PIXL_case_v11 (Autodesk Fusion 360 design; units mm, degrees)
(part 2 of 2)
sketch "Sketch25" plane through (0, 0, -9.2) normal (0, 0, 1) x axis (1, 0, 0)
  line L1 (4.375, -8.325) -> (3.775, -8.325)
  line L2 (4.375, -7.725) -> (4.375, -8.325)
  line L3 (3.775, -7.725) -> (4.375, -7.725)
  line L4 (3.775, -8.325) -> (3.775, -7.725)
  line L5 (6.075, -8.325) -> (5.475, -8.325)
  line L6 (6.075, -7.725) -> (6.075, -8.325)
  line L7 (5.475, -7.725) -> (6.075, -7.725)
  line L8 (5.475, -8.325) -> (5.475, -7.725)
  line L9 (3.525, -7.475) -> (2.925, -7.475)
  line L10 (3.525, -6.875) -> (3.525, -7.475)
  line L11 (2.925, -6.875) -> (3.525, -6.875)
  line L12 (2.925, -7.475) -> (2.925, -6.875)
  line L13 (5.225, -7.475) -> (4.625, -7.475)
  line L14 (5.225, -6.875) -> (5.225, -7.475)
  line L15 (4.625, -6.875) -> (5.225, -6.875)
  line L16 (4.625, -7.475) -> (4.625, -6.875)
  line L17 (6.925, -7.475) -> (6.325, -7.475)
  line L18 (6.925, -6.875) -> (6.925, -7.475)
  line L19 (6.325, -6.875) -> (6.925, -6.875)
  line L20 (6.325, -7.475) -> (6.325, -6.875)
  line L21 (2.675, -6.625) -> (2.075, -6.625)
  line L22 (2.675, -6.025) -> (2.675, -6.625)
  line L23 (2.075, -6.025) -> (2.675, -6.025)
  line L24 (2.075, -6.625) -> (2.075, -6.025)
  line L25 (4.375, -6.625) -> (3.775, -6.625)
  line L26 (4.375, -6.025) -> (4.375, -6.625)
  line L27 (3.775, -6.025) -> (4.375, -6.025)
  line L28 (3.775, -6.625) -> (3.775, -6.025)
  line L29 (6.075, -6.625) -> (5.475, -6.625)
  line L30 (6.075, -6.025) -> (6.075, -6.625)
  line L31 (5.475, -6.025) -> (6.075, -6.025)
  line L32 (5.475, -6.625) -> (5.475, -6.025)
  line L33 (3.525, -5.775) -> (2.925, -5.775)
  line L34 (3.525, -5.175) -> (3.525, -5.775)
  line L35 (2.925, -5.175) -> (3.525, -5.175)
  line L36 (2.925, -5.775) -> (2.925, -5.175)
  line L37 (5.225, -5.775) -> (4.625, -5.775)
  line L38 (5.225, -5.175) -> (5.225, -5.775)
  line L39 (4.625, -5.175) -> (5.225, -5.175)
  line L40 (4.625, -5.775) -> (4.625, -5.175)
  line L41 (6.925, -5.775) -> (6.325, -5.775)
  line L42 (6.925, -5.175) -> (6.925, -5.775)
  line L43 (6.325, -5.175) -> (6.925, -5.175)
  line L44 (6.325, -5.775) -> (6.325, -5.175)
  line L45 (2.675, -4.925) -> (2.075, -4.925)
  line L46 (2.675, -4.325) -> (2.675, -4.925)
  line L47 (2.075, -4.325) -> (2.675, -4.325)
  line L48 (2.075, -4.925) -> (2.075, -4.325)
  line L49 (4.375, -4.925) -> (3.775, -4.925)
  line L50 (4.375, -4.325) -> (4.375, -4.925)
  line L51 (3.775, -4.325) -> (4.375, -4.325)
  line L52 (3.775, -4.925) -> (3.775, -4.325)
  line L53 (6.075, -4.925) -> (5.475, -4.925)
  line L54 (6.075, -4.325) -> (6.075, -4.925)
  line L55 (5.475, -4.325) -> (6.075, -4.325)
  line L56 (5.475, -4.925) -> (5.475, -4.325)
  line L57 (3.525, -4.075) -> (2.925, -4.075)
  line L58 (3.525, -3.475) -> (3.525, -4.075)
  line L59 (2.925, -3.475) -> (3.525, -3.475)
  line L60 (2.925, -4.075) -> (2.925, -3.475)
  line L61 (5.225, -4.075) -> (4.625, -4.075)
  line L62 (5.225, -3.475) -> (5.225, -4.075)
  line L63 (4.625, -3.475) -> (5.225, -3.475)
  line L64 (4.625, -4.075) -> (4.625, -3.475)
extrude "Extrude25" cut sketch "Sketch25" along normal blind 0.3
work_plane "WorkPlane26" AlongDistance -9.2 ExtraOffset 0
sketch "Sketch26" plane through (0, 0, -9.2) normal (0, 0, 1) x axis (1, 0, 0)
  line L1 (15.05, -9.65) -> (11.95, -9.65)
  line L2 (17.25, -4.35) -> (17.25, -7.45)
  line L3 (11.95, -2.15) -> (15.05, -2.15)
  line L4 (9.75, -7.45) -> (9.75, -4.35)
  arc A1 centre (15.05, -7.45) radius 2.2 clockwise from (17.25, -7.45) to (15.05, -9.65)
  arc A2 centre (15.05, -4.35) radius 2.2 clockwise from (15.05, -2.15) to (17.25, -4.35)
  arc A3 centre (11.95, -4.35) radius 2.2 clockwise from (9.75, -4.35) to (11.95, -2.15)
  arc A4 centre (11.95, -7.45) radius 2.2 clockwise from (11.95, -9.65) to (9.75, -7.45)
extrude "Extrude26" cut sketch "Sketch26" along normal blind 0.3
work_plane "WorkPlane1" AlongDistance -5.8 ExtraOffset 0
sketch "Sketch1" plane through (0, 0, -5.8) normal (0, 0, 1) x axis (1, 0, 0)
  line L1 (8.4, -6.9) -> (-21.6, -6.9)
  line L2 (8.4, 13.1) -> (8.4, -6.9)
  line L3 (-21.6, 13.1) -> (8.4, 13.1)
  line L4 (-21.6, -6.9) -> (-21.6, 13.1)
extrude "Extrude1" new body sketch "Sketch1" along normal blind 5 bodies "LiPo 30x20x5"
work_plane "WorkPlane2" AlongDistance -6.5 ExtraOffset 0
sketch "Sketch2" plane through (0, 0, -6.5) normal (0, 0, 1) x axis (1, 0, 0)
  circle C1 centre (15.5, 4) radius 5
extrude "Extrude2" new body sketch "Sketch2" along normal blind 2.7 bodies "Vibration motor 10x2.7"
work_plane "WorkPlane3" AlongDistance -1.3 ExtraOffset 0
sketch "Sketch3" plane through (0, 0, -1.3) normal (0, 0, 1) x axis (1, 0, 0)
  line L1 (21.6, -24.9) -> (0.6, -24.9)
  line L2 (21.6, -7.1) -> (21.6, -24.9)
  line L3 (0.6, -7.1) -> (21.6, -7.1)
  line L4 (0.6, -24.9) -> (0.6, -7.1)
extrude "Extrude3" new body sketch "Sketch3" along normal blind 1 bodies "XIAO ESP32-S3 (upside down)"
work_plane "WorkPlane4" AlongDistance -4.5 ExtraOffset 0
sketch "Sketch4" plane through (0, 0, -4.5) normal (0, 0, 1) x axis (1, 0, 0)
  line L1 (22, -20.45) -> (14.6, -20.45)
  line L2 (22, -11.55) -> (22, -20.45)
  line L3 (14.6, -11.55) -> (22, -11.55)
  line L4 (14.6, -20.45) -> (14.6, -11.55)
extrude "Extrude4" add sketch "Sketch4" along normal blind 3.2
work_plane "WorkPlane5" AlongDistance -3.8 ExtraOffset 0
sketch "Sketch5" plane through (0, 0, -3.8) normal (0, 0, 1) x axis (1, 0, 0)
  line L1 (14.6, -23.9) -> (1.6, -23.9)
  line L2 (14.6, -8.1) -> (14.6, -23.9)
  line L3 (1.6, -8.1) -> (14.6, -8.1)
  line L4 (1.6, -23.9) -> (1.6, -8.1)
extrude "Extrude5" add sketch "Sketch5" along normal blind 2.5
work_plane "WorkPlane6" AlongDistance -6.5 ExtraOffset 0
sketch "Sketch6" plane through (0, 0, -6.5) normal (0, 0, 1) x axis (1, 0, 0)
  line L1 (-4, -24.9) -> (-18, -24.9)
  line L2 (-4, -10.9) -> (-4, -24.9)
  line L3 (-18, -10.9) -> (-4, -10.9)
  line L4 (-18, -24.9) -> (-18, -10.9)
extrude "Extrude6" new body sketch "Sketch6" along normal blind 6.2 bodies "DS3231 14x14 (no header)"
work_plane "WorkPlane7" AlongDistance -8.3 ExtraOffset 0
sketch "Sketch7" plane through (0, 0, -8.3) normal (0, 0, 1) x axis (1, 0, 0)
  circle C1 centre (11, -15.3) radius 10
extrude "Extrude7" new body sketch "Sketch7" along normal blind 0.5 bodies "Piezo disc 20mm"
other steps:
create_component "CreateComponent1"
create_component "CreateComponent71"
create_component "CreateComponent72"
create_component "CreateComponent73"
named bodies: "Shell", "Back", "LiPo 30x20x5", "Vibration motor 10x2.7", "XIAO ESP32-S3 (upside down)", "DS3231 14x14 (no header)", "Piezo disc 20mm"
